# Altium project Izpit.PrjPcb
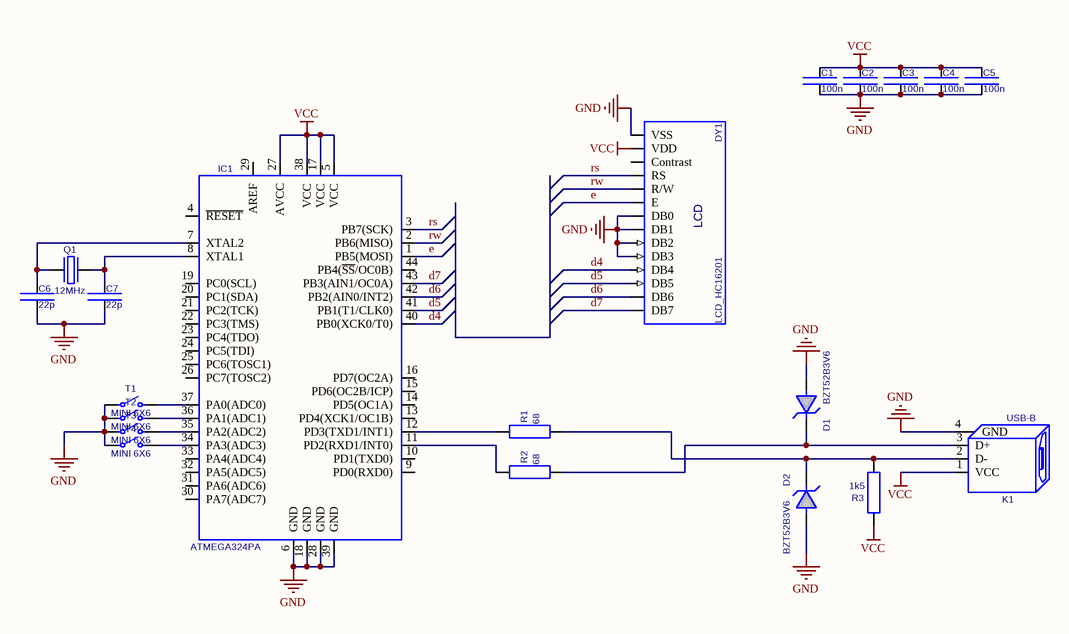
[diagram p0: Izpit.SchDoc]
1 sheet, 20 parts. Net scope: global (net labels, ports and power ports of the same name join across sheets).
Board file: Izpit.PcbDoc

## Sheet Izpit.SchDoc
size A4

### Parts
C1  100n  [C0805]
C2  100n  [C0805]
C3  100n  [C0805]
C4  100n  [C0805]
C5  100n  [C0805]
C6  22p  [C0805]
C7  22p  [C0805]
D1  BZT52B3V6  [SOD-123]
D2  BZT52B3V6  [SOD-123]
DY1  LCD_HC16201  [_LCD_LCD_HC16201(Primary)]
IC1  ATMEGA324PA  [TQFP44]
K1  USB-B  [_USB_B_90_F_USB-B-90F(Primary)]
Q1  12MHz  [Crystal_HC49]
R1  68  [R0805]
R2  68  [R0805]
R3  1k5  [R0805]
T1  MINI 6X6  [SW 5x6 SMD SHORT]
T2  MINI 6X6  [SW 5x6 SMD SHORT]
T3  MINI 6X6  [SW 5x6 SMD SHORT]
T4  MINI 6X6  [SW 5x6 SMD SHORT]

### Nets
GND: C1.2 C2.2 C3.2 C4.2 C5.2 C6.2 C7.2 D1.2 D2.2 DY1.DB0 DY1.DB1 DY1.DB2 DY1.DB3 DY1.VSS IC1.6(GND) IC1.18(GND) IC1.28(GND) IC1.39(GND) K1.4(GND) T1.1 T2.1 T3.1 T4.1
VCC: C1.1 C2.1 C3.1 C4.1 C5.1 DY1.VDD IC1.5(VCC) IC1.17(VCC) IC1.27(AVCC) IC1.38(VCC) K1.1(VCC) R3.1
d4: DY1.DB4 IC1.40(PB0(XCK0/T0))
d5: DY1.DB5 IC1.41(PB1(T1/CLK0))
d6: DY1.DB6 IC1.42(PB2(AIN0/INT2))
d7: DY1.DB7 IC1.43(PB3(AIN1/OC0A))
e: DY1.E IC1.1(PB5(MOSI))
rs: DY1.RS IC1.3(PB7(SCK))
rw: DY1.R/W IC1.2(PB6(MISO))
NetC6_1: C6.1 IC1.7(XTAL2) Q1.2
NetC7_1: C7.1 IC1.8(XTAL1) Q1.1
NetD1_1: D1.1 K1.3(D+) R2.2
NetD2_1: D2.1 K1.2(D-) R1.2 R3.2
NetIC1_11: IC1.11(PD2(RXD1/INT0)) R2.1
NetIC1_12: IC1.12(PD3(TXD1/INT1)) R1.1
NetIC1_34: IC1.34(PA3(ADC3)) T4.2
NetIC1_35: IC1.35(PA2(ADC2)) T3.2
NetIC1_36: IC1.36(PA1(ADC1)) T2.2
NetIC1_37: IC1.37(PA0(ADC0)) T1.2

Not connected (* = marked no-connect by the designer): DY1 Contrast; IC1 4(~{RESET}) 9(PD0(RXD0)) 10(PD1(TXD0)) 13(PD4(XCK1/OC1B)) 14(PD5(OC1A)) 15(PD6(OC2B/ICP)) 16(PD7(OC2A)) 19(PC0(SCL)) 20(PC1(SDA)) 21(PC2(TCK)) 22(PC3(TMS)) 23(PC4(TDO)) 24(PC5(TDI)) 25(PC6(TOSC1)) 26(PC7(TOSC2)) 29(AREF) 30(PA7(ADC7)) 31(PA6(ADC6)) 32(PA5(ADC5)) 33(PA4(ADC4)) 44(PB4(~{SS}/OC0B))

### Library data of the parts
C1-C7 = C: Capacitor
D1 D2 = BZT52B5V1
Q1 = Crystal
R1-R3 = R
T1-T4 = MINI 6X6: pin to pad: 1>1+4 2>2+3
